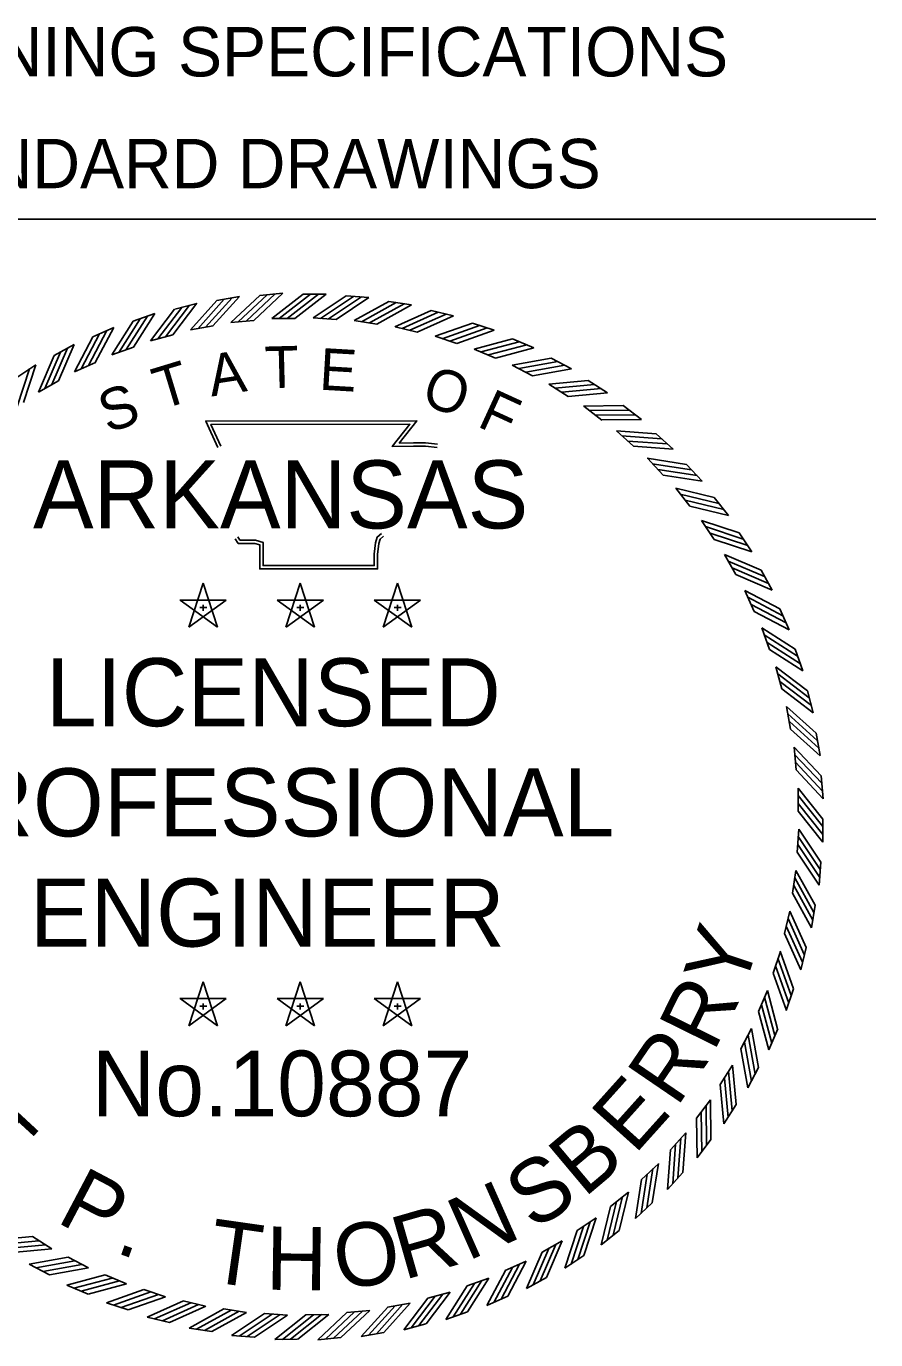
# Model space of a CAD drawing. Extents: x -1197 to 1681, y -1031 to 1021.
# Drawn here: x 1479.2 to 1680.9, y 624.2 to 936 of the extents above; entities that cross this region are included whole.
import ezdxf

# ---------------------------------------------------------------- set-up
doc = ezdxf.new("R2010")
doc.units = 0
doc.layers.add('R_Border Prem', color=7, linetype='Continuous')
doc.layers.add('R_Grid', color=7, linetype='Continuous')

msp = doc.modelspace()

# ---------------------------------------------------------------- linework, layer by layer
at = {"layer": 'R_Border Prem'}
msp.add_line((1249.94, 890.16), (1680.94, 890.16), dxfattribs=at)
at = {"layer": 'R_Grid'}
for p, q in [((1514.42, 868.83), (1519.68, 870.21)), ((1524.46, 870.88), (1529.82, 871.83)), ((1534.65, 872.1), (1540.07, 872.6)), ((1544.95, 872.4), (1550.39, 872.4)), ((1555.14, 872), (1560.57, 871.6)), ((1565.31, 870.67), (1570.69, 869.83)), ((1504.57, 865.95), (1509.7, 867.77)), ((1575.34, 868.52), (1580.63, 867.23)), ((1495, 862.27), (1499.96, 864.51)), ((1518.16, 863.89), (1523.53, 864.84)), ((1527.79, 865.65), (1533.22, 866.15)), ((1537.53, 866.61), (1542.98, 866.61)), ((1547.31, 866.77), (1552.75, 866.37)), ((1557.08, 866.11), (1562.47, 865.26)), ((1566.76, 864.65), (1572.05, 863.36)), ((1585.15, 865.54), (1590.32, 863.82)), ((1508.71, 861.34), (1513.98, 862.73)), ((1576.28, 862.4), (1581.45, 860.67)), ((1594.69, 861.77), (1599.69, 859.63)), ((1485.76, 857.82), (1490.52, 860.45)), ((1499.5, 858.02), (1504.64, 859.84)), ((1585.59, 859.36), (1590.6, 857.22)), ((1476.92, 852.61), (1481.45, 855.63)), ((1490.6, 853.95), (1495.58, 856.19)), ((1594.61, 855.57), (1599.43, 853.02)), ((1603.88, 857.21), (1608.69, 854.67)), ((1482.07, 849.16), (1486.84, 851.8)), ((1612.66, 851.92), (1617.25, 848.99)), ((1603.29, 851.05), (1607.88, 848.11)), ((1611.57, 845.82), (1615.9, 842.51)), ((1620.98, 845.92), (1625.3, 842.62)), ((1619.38, 839.93), (1623.43, 836.28)), ((1628.77, 839.25), (1632.81, 835.6)), ((1626.69, 833.42), (1630.42, 829.44)), ((1635.99, 831.96), (1639.71, 827.99)), ((1633.43, 826.32), (1636.81, 822.05)), ((1642.58, 824.1), (1645.96, 819.84)), ((1639.56, 818.69), (1642.58, 814.15)), ((1648.49, 815.72), (1651.51, 811.2)), ((1645.04, 810.58), (1647.68, 805.81)), ((1653.7, 806.89), (1656.33, 802.13)), ((1521.18, 803.76), (1517.77, 793.31)), ((1524.57, 793.32), (1521.18, 803.77)), ((1544.25, 803.76), (1540.85, 793.31)), ((1547.65, 793.32), (1544.26, 803.77)), ((1567.33, 803.76), (1563.93, 793.31)), ((1570.72, 793.32), (1567.34, 803.77)), ((1649.83, 802.05), (1652.07, 797.07)), ((1526.66, 799.77), (1515.68, 799.78)), ((1515.69, 799.77), (1524.57, 793.31)), ((1517.78, 793.32), (1526.68, 799.77)), ((1521.19, 798.6), (1521.19, 797.22)), ((1549.74, 799.77), (1538.76, 799.78)), ((1538.77, 799.77), (1547.65, 793.31)), ((1540.86, 793.32), (1549.75, 799.77)), ((1544.26, 798.6), (1544.26, 797.22)), ((1572.82, 799.77), (1561.84, 799.78)), ((1561.84, 799.77), (1570.72, 793.31)), ((1563.94, 793.32), (1572.83, 799.77)), ((1567.34, 798.6), (1567.34, 797.22)), ((1520.39, 798.02), (1522.03, 798.02)), ((1543.47, 798.02), (1545.1, 798.02)), ((1566.55, 798.02), (1568.18, 798.02)), ((1658.15, 797.65), (1660.39, 792.69)), ((1653.9, 793.15), (1655.72, 788)), ((1661.83, 788.08), (1663.65, 782.95)), ((1657.22, 783.94), (1658.61, 778.67)), ((1664.71, 778.23), (1666.09, 772.97)), ((1659.77, 774.49), (1660.72, 769.12)), ((1666.76, 768.18), (1667.71, 762.83)), ((1661.53, 764.86), (1662.03, 759.43)), ((1667.98, 758), (1668.48, 752.58)), ((1662.49, 755.12), (1662.54, 749.67)), ((1662.65, 745.34), (1662.25, 739.9)), ((1668.35, 747.75), (1668.4, 742.31)), ((1667.88, 737.51), (1667.48, 732.08)), ((1661.99, 735.57), (1661.14, 730.18)), ((1666.55, 727.34), (1665.71, 721.96)), ((1660.53, 725.89), (1659.24, 720.59)), ((1664.4, 717.31), (1663.11, 712.02)), ((1658.28, 716.37), (1656.55, 711.19)), ((1521.18, 709.13), (1517.77, 698.69)), ((1524.57, 698.69), (1521.18, 709.14)), ((1544.25, 709.13), (1540.85, 698.69)), ((1547.65, 698.69), (1544.26, 709.14)), ((1567.33, 709.13), (1563.93, 698.69)), ((1570.72, 698.69), (1567.34, 709.14)), ((1526.66, 705.15), (1515.68, 705.16)), ((1515.69, 705.15), (1524.57, 698.68)), ((1517.78, 698.69), (1526.68, 705.14)), ((1549.74, 705.15), (1538.76, 705.16)), ((1538.77, 705.15), (1547.65, 698.68)), ((1540.86, 698.69), (1549.75, 705.14)), ((1572.82, 705.15), (1561.84, 705.16)), ((1561.84, 705.15), (1570.72, 698.68)), ((1563.94, 698.69), (1572.83, 705.14)), ((1655.24, 707.06), (1653.1, 702.05)), ((1661.42, 707.49), (1659.7, 702.33)), ((1520.39, 703.39), (1522.03, 703.39)), ((1521.19, 703.98), (1521.19, 702.6)), ((1543.47, 703.39), (1545.1, 703.39)), ((1544.26, 703.98), (1544.26, 702.6)), ((1566.55, 703.39), (1568.18, 703.39)), ((1567.34, 703.98), (1567.34, 702.6)), ((1651.45, 698.04), (1648.9, 693.22)), ((1657.65, 697.96), (1655.51, 692.96)), ((1646.93, 689.36), (1643.99, 684.77)), ((1653.09, 688.77), (1650.55, 683.96)), ((1641.7, 681.08), (1638.39, 676.75)), ((1647.8, 679.98), (1644.87, 675.4)), ((1635.81, 673.27), (1632.16, 669.22)), ((1641.8, 671.67), (1638.5, 667.34)), ((1629.3, 665.96), (1625.32, 662.23)), ((1635.13, 663.88), (1631.48, 659.84)), ((1622.2, 659.22), (1617.93, 655.83)), ((1627.84, 656.66), (1623.87, 652.94)), ((1614.57, 653.09), (1610.03, 650.07)), ((1485.24, 645.72), (1480.65, 648.66)), ((1619.98, 650.07), (1615.72, 646.69)), ((1606.46, 647.61), (1601.69, 644.97)), ((1493.92, 641.2), (1489.1, 643.75)), ((1597.93, 642.82), (1592.95, 640.58)), ((1611.6, 644.16), (1607.08, 641.14)), ((1484.65, 639.55), (1479.84, 642.1)), ((1502.94, 637.41), (1497.93, 639.55)), ((1493.84, 635), (1488.84, 637.14)), ((1589.03, 638.75), (1583.88, 636.93)), ((1602.77, 638.95), (1598.01, 636.32)), ((1512.25, 634.37), (1507.07, 636.1)), ((1521.77, 632.12), (1516.47, 633.41)), ((1579.82, 635.43), (1574.55, 634.04)), ((1593.53, 634.49), (1588.57, 632.26)), ((1503.37, 631.23), (1498.21, 632.95)), ((1531.45, 630.66), (1526.06, 631.51)), ((1541.22, 630), (1535.78, 630.4)), ((1551, 630.15), (1545.55, 630.1)), ((1560.74, 631.11), (1555.31, 630.61)), ((1570.37, 632.88), (1565, 631.93)), ((1583.96, 630.81), (1578.83, 629)), ((1513.19, 628.25), (1507.9, 629.54)), ((1523.22, 626.09), (1517.84, 626.94)), ((1574.11, 627.94), (1568.85, 626.55)), ((1533.39, 624.77), (1527.96, 625.17)), ((1543.63, 624.3), (1538.19, 624.25)), ((1553.88, 624.67), (1548.46, 624.17)), ((1564.06, 625.89), (1558.71, 624.94))]:
    msp.add_line(p, q, dxfattribs=at)
for points in [[(1513.98, 862.73), (1519.68, 870.22)], [(1518.15, 863.89), (1524.46, 870.88)], [(1519.88, 864.17), (1526.19, 871.17)], [(1521.73, 864.54), (1528.04, 871.53)], [(1523.52, 864.84), (1529.83, 871.83)], [(1527.78, 865.65), (1534.64, 872.09)], [(1529.53, 865.79), (1536.39, 872.24)], [(1531.4, 866.01), (1538.26, 872.45)], [(1533.21, 866.16), (1540.07, 872.6)], [(1537.52, 866.61), (1544.94, 872.4)], [(1539.27, 866.59), (1546.69, 872.38)], [(1541.16, 866.63), (1548.58, 872.42)], [(1542.97, 866.62), (1550.4, 872.41)], [(1547.31, 866.76), (1555.13, 871.99)], [(1549.05, 866.62), (1556.88, 871.85)], [(1550.94, 866.52), (1558.77, 871.75)], [(1552.75, 866.37), (1560.57, 871.6)], [(1557.07, 866.11), (1565.3, 870.67)], [(1558.8, 865.82), (1567.03, 870.38)], [(1560.67, 865.57), (1568.91, 870.13)], [(1502.92, 859.25), (1507.99, 867.18)], [(1504.64, 859.84), (1509.7, 867.77)], [(1508.7, 861.34), (1514.41, 868.82)], [(1510.4, 861.77), (1516.11, 869.25)], [(1512.22, 862.29), (1517.92, 869.77)], [(1562.46, 865.27), (1570.69, 869.83)], [(1566.75, 864.65), (1575.33, 868.52)], [(1568.45, 864.22), (1577.03, 868.09)], [(1570.29, 863.81), (1578.87, 867.68)], [(1572.05, 863.37), (1580.63, 867.23)], [(1493.91, 855.46), (1498.3, 863.78)], [(1495.57, 856.19), (1499.96, 864.51)], [(1499.5, 858.01), (1504.57, 865.95)], [(1501.15, 858.58), (1506.22, 866.51)], [(1576.27, 862.39), (1585.15, 865.54)], [(1577.93, 861.82), (1586.8, 864.97)], [(1579.74, 861.27), (1588.61, 864.41)], [(1581.45, 860.68), (1590.32, 863.83)], [(1490.6, 853.94), (1494.99, 862.27)], [(1492.2, 854.65), (1496.6, 862.97)], [(1585.58, 859.36), (1594.68, 861.76)], [(1587.18, 858.66), (1596.28, 861.06)], [(1482.06, 849.15), (1485.76, 857.81)], [(1483.6, 849.98), (1487.3, 858.64)], [(1485.24, 850.93), (1488.93, 859.59)], [(1486.83, 851.8), (1490.53, 860.46)], [(1588.94, 857.95), (1598.04, 860.36)], [(1590.6, 857.22), (1599.7, 859.63)], [(1476.97, 845.71), (1479.94, 854.64)], [(1478.49, 846.7), (1481.45, 855.64)], [(1594.6, 855.57), (1603.87, 857.21)], [(1596.14, 854.74), (1605.41, 856.38)], [(1597.83, 853.89), (1607.1, 855.53)], [(1599.43, 853.03), (1608.69, 854.67)], [(1603.28, 851.05), (1612.65, 851.92)], [(1604.75, 850.09), (1614.12, 850.96)], [(1606.36, 849.1), (1615.73, 849.98)], [(1607.88, 848.11), (1617.25, 848.99)], [(1611.56, 845.82), (1620.97, 845.92)], [(1524.68, 835.99), (1521.78, 842.27), (1571.96, 842.3), (1567.77, 837.03), (1571.17, 837.08), (1574.02, 837.11), (1576.87, 836.8)], [(1612.94, 844.75), (1622.35, 844.84)], [(1614.47, 843.63), (1623.88, 843.73)], [(1615.9, 842.52), (1625.31, 842.62)], [(1525.4, 836.32), (1523.02, 841.48), (1570.31, 841.5), (1566.1, 836.22), (1571.18, 836.28), (1573.98, 836.32), (1576.78, 836.01)], [(1619.37, 839.93), (1628.76, 839.25)], [(1620.66, 838.75), (1630.05, 838.06)], [(1622.09, 837.51), (1631.48, 836.83)], [(1623.43, 836.28), (1632.81, 835.6)], [(1626.68, 833.42), (1635.98, 831.96)], [(1627.86, 832.13), (1637.16, 830.67)], [(1629.19, 830.78), (1638.49, 829.32)], [(1630.41, 829.45), (1639.71, 827.99)], [(1633.42, 826.32), (1642.57, 824.1)], [(1634.49, 824.94), (1643.64, 822.72)], [(1635.7, 823.48), (1644.85, 821.27)], [(1636.81, 822.05), (1645.96, 819.84)], [(1639.55, 818.69), (1648.48, 815.73)], [(1640.51, 817.23), (1649.44, 814.26)], [(1564.05, 814.96), (1563.2, 814.26), (1562.91, 813.22), (1562.63, 810.62), (1562.63, 807.15), (1534.62, 807.15), (1534.62, 811.84), (1534.62, 812.88), (1533.48, 813.22), (1529.5, 813.22), (1528.79, 814.3)], [(1563.55, 815.58), (1562.5, 814.72), (1562.13, 813.37), (1561.83, 810.67), (1561.83, 807.95), (1535.41, 807.95), (1535.41, 811.84), (1535.41, 813.47), (1533.6, 814.02), (1529.93, 814.02), (1529.45, 814.74)], [(1641.59, 815.68), (1650.52, 812.71)], [(1642.58, 814.16), (1651.52, 811.19)], [(1645.03, 810.58), (1653.69, 806.89)], [(1645.86, 809.04), (1654.52, 805.35)], [(1646.81, 807.41), (1655.47, 803.72)], [(1647.68, 805.82), (1656.34, 802.12)], [(1649.82, 802.05), (1658.15, 797.65)], [(1650.53, 800.45), (1658.85, 796.05)], [(1651.34, 798.74), (1659.66, 794.34)], [(1652.07, 797.08), (1660.39, 792.68)], [(1653.89, 793.15), (1661.83, 788.08)], [(1654.46, 791.49), (1662.39, 786.43)], [(1655.13, 789.73), (1663.06, 784.66)], [(1655.72, 788.01), (1663.65, 782.94)], [(1657.22, 783.94), (1664.7, 778.24)], [(1657.65, 782.25), (1665.13, 776.54)], [(1658.17, 780.43), (1665.65, 774.72)], [(1658.61, 778.67), (1666.1, 772.97)], [(1659.77, 774.5), (1666.76, 768.19)], [(1660.05, 772.77), (1667.05, 766.46)], [(1660.42, 770.91), (1667.41, 764.61)], [(1660.72, 769.13), (1667.71, 762.82)], [(1661.53, 764.87), (1667.97, 758.01)], [(1661.67, 763.12), (1668.12, 756.26)], [(1661.89, 761.25), (1668.33, 754.38)], [(1662.04, 759.44), (1668.48, 752.58)], [(1662.49, 755.13), (1668.35, 747.76)], [(1662.49, 753.38), (1668.35, 746.01)], [(1662.55, 751.49), (1668.41, 744.12)], [(1662.55, 749.68), (1668.41, 742.31)], [(1662.64, 745.34), (1667.87, 737.51)], [(1662.5, 743.6), (1667.73, 735.77)], [(1662.25, 739.9), (1667.48, 732.07)], [(1662.4, 741.71), (1667.63, 733.88)], [(1661.7, 733.85), (1666.26, 725.62)], [(1661.99, 735.58), (1666.55, 727.34)], [(1661.15, 730.19), (1665.71, 721.96)], [(1661.45, 731.98), (1666.01, 723.74)], [(1660.1, 724.2), (1663.97, 715.62)], [(1660.53, 725.9), (1664.4, 717.32)], [(1659.25, 720.6), (1663.11, 712.02)], [(1659.69, 722.36), (1663.56, 713.77)], [(1657.7, 714.72), (1660.85, 705.85)], [(1658.27, 716.38), (1661.42, 707.5)], [(1656.56, 711.2), (1659.71, 702.33)], [(1657.15, 712.91), (1660.29, 704.04)], [(1654.54, 705.47), (1656.94, 696.36)], [(1655.24, 707.07), (1657.64, 697.97)], [(1653.1, 702.05), (1655.51, 692.95)], [(1653.83, 703.71), (1656.24, 694.61)], [(1650.62, 696.51), (1652.26, 687.24)], [(1651.45, 698.05), (1653.09, 688.78)], [(1648.91, 693.22), (1650.55, 683.95)], [(1649.77, 694.82), (1651.41, 685.55)], [(1646.93, 689.37), (1647.8, 679.99)], [(1644.98, 686.29), (1645.86, 676.91)], [(1645.97, 687.9), (1646.84, 678.53)], [(1643.99, 684.77), (1644.87, 675.4)], [(1641.7, 681.09), (1641.8, 671.68)], [(1638.4, 676.75), (1638.5, 667.34)], [(1639.51, 678.18), (1639.61, 668.77)], [(1640.63, 679.71), (1640.72, 670.3)], [(1633.39, 670.56), (1632.71, 661.17)], [(1634.63, 671.99), (1633.94, 662.6)], [(1635.81, 673.27), (1635.13, 663.89)], [(1632.16, 669.22), (1631.48, 659.83)], [(1628.01, 664.79), (1626.55, 655.48)], [(1629.3, 665.97), (1627.84, 656.67)], [(1625.33, 662.23), (1623.87, 652.93)], [(1626.66, 663.46), (1625.2, 654.16)], [(1620.82, 658.16), (1618.6, 649.01)], [(1622.2, 659.23), (1619.98, 650.08)], [(1617.93, 655.83), (1615.72, 646.69)], [(1619.36, 656.95), (1617.15, 647.8)], [(1613.11, 652.14), (1610.14, 643.21)], [(1614.57, 653.1), (1611.61, 644.16)], [(1480.65, 648.65), (1471.28, 647.78)], [(1610.04, 650.07), (1607.07, 641.13)], [(1611.56, 651.06), (1608.59, 642.12)], [(1482.17, 647.66), (1472.79, 646.79)], [(1483.78, 646.68), (1474.41, 645.81)], [(1485.25, 645.72), (1475.87, 644.85)], [(1603.29, 645.83), (1599.6, 637.17)], [(1604.92, 646.79), (1601.23, 638.13)], [(1606.46, 647.62), (1602.77, 638.96)], [(1489.1, 643.74), (1479.83, 642.1)], [(1490.7, 642.88), (1481.43, 641.24)], [(1597.93, 642.83), (1593.53, 634.5)], [(1601.7, 644.97), (1598, 636.31)], [(1492.39, 642.03), (1483.12, 640.39)], [(1493.93, 641.2), (1484.66, 639.55)], [(1497.93, 639.54), (1488.83, 637.14)], [(1592.96, 640.58), (1588.56, 632.26)], [(1594.62, 641.31), (1590.22, 632.99)], [(1596.33, 642.12), (1591.93, 633.8)], [(1499.59, 638.82), (1490.49, 636.41)], [(1501.35, 638.11), (1492.24, 635.71)], [(1502.95, 637.41), (1493.85, 635)], [(1583.89, 636.93), (1578.82, 629)], [(1585.61, 637.52), (1580.54, 629.58)], [(1587.37, 638.19), (1582.31, 630.25)], [(1589.03, 638.76), (1583.96, 630.82)], [(1507.08, 636.09), (1498.21, 632.94)], [(1508.79, 635.5), (1499.92, 632.35)], [(1510.6, 634.94), (1501.73, 631.8)], [(1512.26, 634.38), (1503.38, 631.23)], [(1516.48, 633.4), (1507.9, 629.53)], [(1574.55, 634.04), (1568.85, 626.55)], [(1576.31, 634.48), (1570.6, 626.99)], [(1578.13, 635), (1572.42, 627.52)], [(1579.82, 635.43), (1574.12, 627.95)], [(1518.24, 632.96), (1509.65, 629.09)], [(1520.08, 632.55), (1511.5, 628.68)], [(1521.78, 632.12), (1513.2, 628.25)], [(1526.07, 631.5), (1517.84, 626.94)], [(1527.86, 631.2), (1519.62, 626.64)], [(1529.73, 630.95), (1521.5, 626.39)], [(1531.46, 630.66), (1523.22, 626.1)], [(1535.78, 630.4), (1527.95, 625.17)], [(1537.59, 630.25), (1529.76, 625.02)], [(1539.48, 630.15), (1531.65, 624.92)], [(1541.22, 630.01), (1533.39, 624.78)], [(1545.56, 630.1), (1538.19, 624.24)], [(1547.37, 630.1), (1540, 624.24)], [(1549.26, 630.16), (1541.89, 624.3)], [(1551.01, 630.16), (1543.64, 624.3)], [(1555.32, 630.61), (1548.46, 624.16)], [(1557.12, 630.76), (1550.26, 624.31)], [(1559, 630.98), (1552.14, 624.53)], [(1560.75, 631.12), (1553.89, 624.67)], [(1565.01, 631.93), (1558.7, 624.94)], [(1566.79, 632.22), (1560.49, 625.23)], [(1568.65, 632.59), (1562.34, 625.6)], [(1570.38, 632.88), (1564.07, 625.89)]]:
    msp.add_lwpolyline(points, dxfattribs=at)

# ---------------------------------------------------------------- texts
at = {"layer": 'R_Border Prem'}
for s, p in [('INDEX OF SHEETS, GOVERNING SPECIFICATIONS ', (1265.21, 924.09)), ('GENERAL NOTES & STANDARD DRAWINGS', (1286.35, 897.54))]:
    msp.add_text(s, height=11.724, dxfattribs=at).set_placement(p)
at = {"layer": 'R_Grid'}
for s, height, rotation, p in [('A', 9.9, 8.6788, (1523.15, 848.07)), ('T', 9.9, 1.4789, (1535.93, 850.04)), ('E', 9.9, 356.672, (1548.6, 849.74)), ('T', 9.9, 16.9015, (1511.13, 844.93)), ('O', 9.9, 341.2218, (1572.63, 846.34)), ('S', 9.9, 19.7726, (1498.55, 839.28)), ('F', 9.9, 335.3628, (1585.97, 841.13)), ('Y', 15.03, 71.7733, (1649.35, 706.4)), ('R', 15.03, 63.7477, (1642.46, 692.22)), ('R', 15.03, 55.7221, (1633.67, 679.13)), ('E', 15.03, 48.0613, (1623.64, 667.9)), ('T', 15.03, 317.226, (1463.18, 670.7)), ('B', 15.03, 40.0357, (1611.64, 657.68)), ('S', 15.03, 32.7397, (1599.58, 649.93)), ('P', 15.03, 332.1828, (1485.99, 652.27)), ('N', 15.03, 23.9845, (1583.95, 642.73)), ('R', 15.03, 15.9589, (1568.82, 638.3)), ('T', 15.03, 351.882, (1521.83, 638.07)), ('O', 15.03, 7.9332, (1553.22, 636.02)), ('H', 15.03, 359.178, (1536.02, 636.05)), ('.', 15.03, 340.2084, (1499.99, 645))]:
    msp.add_text(s, height=height, rotation=rotation, dxfattribs=at).set_placement(p)
for s, height, p in [('ARKANSAS', 16.155, (1480.76, 816.77)), ('LICENSED', 16.155, (1483.84, 769.81)), ('PROFESSIONAL', 16.1547, (1450.76, 743.66)), ('ENGINEER', 16.155, (1479.99, 717.5)), ('No.10887', 15.578, (1494.76, 677.22))]:
    msp.add_text(s, height=height, dxfattribs=at).set_placement(p)

doc.saveas('drawing.dxf')
